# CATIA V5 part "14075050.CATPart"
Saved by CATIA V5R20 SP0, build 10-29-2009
Part number: 14075050
Definition: NONE
Nomenclature: 14075050
Source: Unknown
Description: 14075050
Bounding box of the stored display mesh (mm): x -25 to 100, y -51.5 to 41.58, z -41.6 to 41.6
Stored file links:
  C:\Users\Utente\Desktop\IO LAVORO\3D X SITO CF\X SITO\PLASTICA\RF2\14075050.CATPart
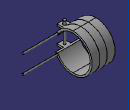
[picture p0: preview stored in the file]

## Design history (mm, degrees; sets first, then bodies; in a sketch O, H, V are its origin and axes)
Body1 "14075050" (main body)
  Solid1: solid without history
